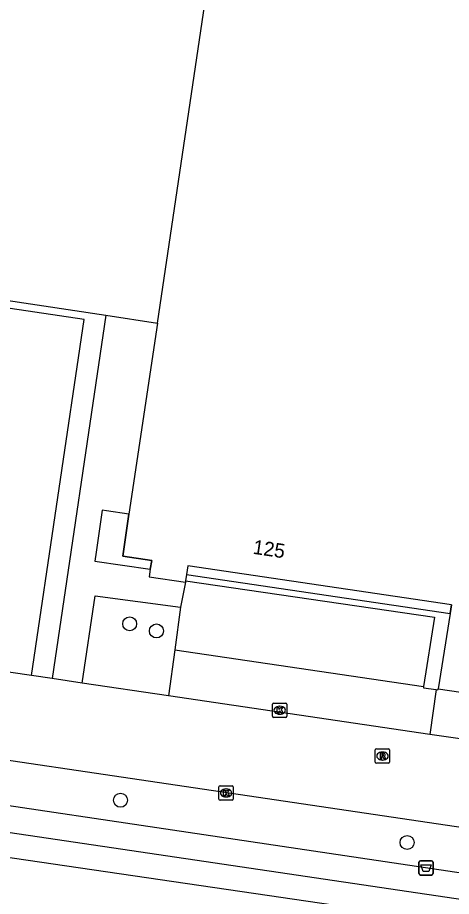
# Model space of a CAD drawing. Extents: x 163686 to 164493, y 382719 to 383870.
# Drawn here: x 163728.6 to 163758.9, y 382784.3 to 382845.8 of the extents above; entities that cross this region are included whole.
import ezdxf

# ---------------------------------------------------------------- set-up
doc = ezdxf.new("R2010")
doc.units = 0
for name, color, linetype in [('IMGEO_Afvalbak', 7, 'Continuous'), ('IMGEO_Boom', 7, 'Continuous'), ('IMGEO_Fietspad_open', 7, 'Continuous'), ('IMGEO_Groenvoorziening', 7, 'Continuous'), ('IMGEO_Kolk', 7, 'Continuous'), ('IMGEO_Pand', 7, 'Continuous'), ('IMGEO_Pand_nummerreeks', 7, 'Continuous'), ('IMGEO_Pand_overbouw', 7, 'Continuous'), ('IMGEO_Parkeervlak_halfverhard', 7, 'Continuous'), ('IMGEO_Parkeervlak_open', 7, 'Continuous'), ('IMGEO_Rijbaan_lokaal_open', 7, 'Continuous'), ('IMGEO_Rioolput', 7, 'Continuous'), ('IMGEO_Voetpad_open', 7, 'Continuous'), ('IMGEO_Waterloop', 7, 'Continuous')]:
    doc.layers.add(name, color=color, linetype=linetype)

msp = doc.modelspace()

# ---------------------------------------------------------------- linework, layer by layer
at = {"layer": 'IMGEO_Afvalbak'}
for p, q in [((163756.643, 382785.871), (163756.643, 382786.671)), ((163756.643, 382786.671), (163756.643, 382785.871)), ((163756.743, 382786.771), (163757.533, 382786.771)), ((163757.533, 382786.771), (163756.743, 382786.771)), ((163757.633, 382786.671), (163757.633, 382785.871)), ((163757.633, 382785.871), (163757.633, 382786.671)), ((163757.533, 382785.771), (163756.743, 382785.771)), ((163756.743, 382785.771), (163757.533, 382785.771))]:
    msp.add_line(p, q, dxfattribs=at)
msp.add_lwpolyline([(163756.786, 382786.485), (163757.49, 382786.485), (163757.341, 382786.015), (163756.935, 382786.015), (163756.786, 382786.485)], dxfattribs=at)
for centre, start, end in [((163756.743, 382786.671), 90, 180), ((163756.743, 382786.671), 90, 180), ((163757.533, 382786.671), 0, 90), ((163757.533, 382786.671), 360, 90), ((163756.743, 382785.871), 180, 270), ((163756.743, 382785.871), 180, 270), ((163757.533, 382785.871), 270, 0), ((163757.533, 382785.871), 270, 0)]:
    msp.add_arc(centre, 0.1, start, end, dxfattribs=at)
at = {"layer": 'IMGEO_Boom'}
for centre in [(163736.411, 382803.347), (163738.281, 382802.85), (163735.772, 382791.006), (163755.814, 382788.046)]:
    msp.add_circle(centre, 0.489, dxfattribs=at)
at = {"layer": 'IMGEO_Fietspad_open'}
for points in [[(163764.154, 382785.228), (163700.855, 382794.642), (163698.697, 382794.967)], [(163938.698, 382757.534), (163796.75, 382778.554), (163700.774, 382792.768), (163698.458, 382793.117)]]:
    msp.add_lwpolyline(points, dxfattribs=at)
at = {"layer": 'IMGEO_Groenvoorziening'}
msp.add_lwpolyline([(163703.742, 382829.606), (163734.753, 382824.935)], dxfattribs=at)
at = {"layer": 'IMGEO_Kolk'}
for p, q in [((163746.406, 382796.879), (163746.406, 382797.731)), ((163746.481, 382797.805), (163747.333, 382797.805)), ((163746.894, 382797.585), (163746.919, 382797.585)), ((163747.407, 382797.731), (163747.407, 382796.879)), ((163746.917, 382797.025), (163746.892, 382797.025)), ((163747.333, 382796.805), (163746.481, 382796.805)), ((163742.656, 382791.087), (163742.656, 382791.939)), ((163742.731, 382792.013), (163743.583, 382792.013)), ((163743.657, 382791.939), (163743.657, 382791.087)), ((163743.144, 382791.793), (163743.169, 382791.793)), ((163743.583, 382791.013), (163742.731, 382791.013)), ((163743.167, 382791.233), (163743.142, 382791.233))]:
    msp.add_line(p, q, dxfattribs=at)
for points in [[(163746.406, 382796.879), (163746.406, 382797.731)], [(163746.481, 382797.805), (163747.333, 382797.805)], [(163746.727, 382797.505), (163746.85, 382797.505), (163746.85, 382797.354), (163746.98, 382797.505), (163747.144, 382797.505), (163746.998, 382797.354), (163747.151, 382797.105), (163746.999, 382797.105), (163746.914, 382797.269), (163746.85, 382797.202), (163746.85, 382797.105), (163746.727, 382797.105), (163746.727, 382797.505)], [(163747.407, 382797.731), (163747.407, 382796.879)], [(163747.333, 382796.805), (163746.481, 382796.805)], [(163742.656, 382791.087), (163742.656, 382791.939)], [(163742.731, 382792.013), (163743.583, 382792.013)], [(163743.657, 382791.939), (163743.657, 382791.087)], [(163742.977, 382791.713), (163743.1, 382791.713), (163743.1, 382791.562), (163743.23, 382791.713), (163743.394, 382791.713), (163743.248, 382791.562), (163743.401, 382791.313), (163743.249, 382791.313), (163743.164, 382791.477), (163743.1, 382791.41), (163743.1, 382791.313), (163742.977, 382791.313), (163742.977, 382791.713)], [(163743.583, 382791.013), (163742.731, 382791.013)]]:
    msp.add_lwpolyline(points, dxfattribs=at)
for centre, start, end in [((163746.483, 382797.729), 91.55205, 178.44795), ((163746.483, 382797.729), 91.55205, 178.44795), ((163747.331, 382797.729), 1.55205, 88.44795), ((163747.331, 382797.729), 1.55205, 88.44795), ((163746.483, 382796.881), 181.55205, 268.44795), ((163746.483, 382796.881), 181.55205, 268.44795), ((163747.331, 382796.881), 271.55205, 358.44795), ((163747.331, 382796.881), 271.55205, 358.44795), ((163742.733, 382791.937), 91.55205, 178.44795), ((163742.733, 382791.937), 91.55205, 178.44795), ((163743.581, 382791.937), 1.55205, 88.44795), ((163743.581, 382791.937), 1.55205, 88.44795), ((163742.733, 382791.089), 181.55205, 268.44795), ((163742.733, 382791.089), 181.55205, 268.44795), ((163743.581, 382791.089), 271.55205, 358.44795), ((163743.581, 382791.089), 271.55205, 358.44795)]:
    msp.add_arc(centre, 0.0765, start, end, dxfattribs=at)
for centre, major_axis, ratio, start_param, end_param in [((163746.893, 382797.305), (-0.387, 0.002), 0.722429, 4.712389, 7.853982), ((163746.918, 382797.305), (-0.39, 0.002), 0.717154, 1.570796, 4.712389), ((163743.143, 382791.513), (-0.387, 0.002), 0.722429, 4.712389, 7.853982), ((163743.168, 382791.513), (-0.39, 0.002), 0.717154, 1.570796, 4.712389)]:
    msp.add_ellipse(centre, major_axis=major_axis, ratio=ratio, start_param=start_param, end_param=end_param, dxfattribs=at)
at = {"layer": 'IMGEO_Pand'}
for points in [[(163738.347, 382824.393), (163744.772, 382867.667), (163767.747, 382864.255), (163761.467, 382821.887)], [(163738.347, 382824.393), (163736.362, 382811.027), (163735.926, 382808.089), (163737.957, 382807.783), (163737.854, 382807.162), (163737.767, 382806.638), (163740.305, 382806.259)], [(163758.915, 382804.671), (163740.469, 382807.408), (163740.381, 382806.79), (163740.32, 382806.366)], [(163740.32, 382806.366), (163740.305, 382806.259)], [(163758.918, 382804.688), (163758.915, 382804.671)]]:
    msp.add_lwpolyline(points, dxfattribs=at)
at = {"layer": 'IMGEO_Pand_overbouw'}
for points in [[(163736.362, 382811.027), (163734.794, 382811.265), (163734.494, 382811.311), (163734.06, 382808.371), (163733.966, 382807.734), (163737.854, 382807.162), (163737.957, 382807.783), (163735.926, 382808.089)], [(163758.915, 382804.671), (163740.469, 382807.408), (163740.381, 382806.79), (163758.827, 382804.076)]]:
    msp.add_lwpolyline(points, close=True, dxfattribs=at)
at = {"layer": 'IMGEO_Parkeervlak_halfverhard'}
msp.add_lwpolyline([(163739.978, 382804.514), (163739.565, 382801.532)], dxfattribs=at)
at = {"layer": 'IMGEO_Parkeervlak_open'}
msp.add_lwpolyline([(163729.55, 382799.728), (163733.236, 382824.631), (163705.132, 382828.814), (163702.804, 382812.996), (163727.391, 382809.337)], dxfattribs=at)
at = {"layer": 'IMGEO_Rijbaan_lokaal_open'}
for points in [[(163734.753, 382824.935), (163730.997, 382799.514)], [(163734.753, 382824.935), (163738.347, 382824.393)], [(163740.305, 382806.259), (163739.978, 382804.514)], [(163733.089, 382799.205), (163733.993, 382805.314), (163739.978, 382804.514)], [(163729.55, 382799.728), (163726.477, 382800.182)], [(163730.997, 382799.514), (163729.55, 382799.728)], [(163733.089, 382799.205), (163730.997, 382799.514)], [(163739.118, 382798.314), (163733.089, 382799.205)], [(163757.401, 382795.612), (163739.118, 382798.314)], [(163701.006, 382797.795), (163761.168, 382788.88)], [(163760.998, 382795.081), (163757.401, 382795.612)]]:
    msp.add_lwpolyline(points, dxfattribs=at)
at = {"layer": 'IMGEO_Rioolput'}
for p, q in [((163753.593, 382793.674), (163753.593, 382794.526)), ((163753.668, 382794.6), (163754.52, 382794.6)), ((163754.594, 382794.526), (163754.594, 382793.674)), ((163754.104, 382793.82), (163754.079, 382793.82)), ((163754.081, 382794.38), (163754.106, 382794.38)), ((163754.52, 382793.6), (163753.668, 382793.6))]:
    msp.add_line(p, q, dxfattribs=at)
for points in [[(163753.593, 382793.674), (163753.593, 382794.526)], [(163753.668, 382794.6), (163754.52, 382794.6)], [(163754.594, 382794.526), (163754.594, 382793.674)], [(163754.182, 382794.298), (163753.93, 382794.3), (163753.93, 382793.9)], [(163753.93, 382793.9), (163754.054, 382793.9), (163754.054, 382794.062), (163754.065, 382794.062)], [(163754.108, 382794.219), (163754.054, 382794.219), (163754.054, 382794.138)], [(163754.054, 382794.138), (163754.106, 382794.138)], [(163754.112, 382794.033), (163754.183, 382793.9), (163754.323, 382793.9), (163754.258, 382794.026)], [(163754.52, 382793.6), (163753.668, 382793.6)]]:
    msp.add_lwpolyline(points, dxfattribs=at)
for centre, radius, start, end in [((163753.67, 382794.524), 0.0765, 91.55205, 178.44795), ((163753.67, 382794.524), 0.0765, 91.55205, 178.44795), ((163754.518, 382794.524), 0.0765, 1.55205, 88.44795), ((163754.518, 382794.524), 0.0765, 1.55205, 88.44795), ((163754.064, 382794.009), 0.0533, 26.02933, 88.69889), ((163754.09, 382794.327), 0.19, 274.7715, 282.96867), ((163754.114, 382794.123), 0.0964, 77.00612, 93.18647), ((163754.128, 382794.18), 0.0378, 276.66336, 79.67722), ((163754.181, 382794.188), 0.109, 350.36119, 89.41601), ((163754.179, 382794.188), 0.112, 277.58423, 350.98172), ((163754.163, 382793.973), 0.108, 29.51342, 73.79051), ((163753.67, 382793.676), 0.0765, 181.55205, 268.44795), ((163753.67, 382793.676), 0.0765, 181.55205, 268.44795), ((163754.518, 382793.676), 0.0765, 271.55205, 358.44795), ((163754.518, 382793.676), 0.0765, 271.55205, 358.44795)]:
    msp.add_arc(centre, radius, start, end, dxfattribs=at)
for centre, major_axis, ratio, start_param, end_param in [((163754.08, 382794.1), (-0.387, 0.002), 0.722429, 4.712389, 7.853982), ((163754.105, 382794.1), (-0.39, 0.002), 0.717154, 1.570796, 4.712389)]:
    msp.add_ellipse(centre, major_axis=major_axis, ratio=ratio, start_param=start_param, end_param=end_param, dxfattribs=at)
at = {"layer": 'IMGEO_Voetpad_open'}
for points in [[(163740.32, 382806.366), (163757.74, 382803.803), (163756.972, 382798.955)], [(163758.915, 382804.671), (163758.827, 382804.076), (163757.985, 382798.809)], [(163739.565, 382801.532), (163739.118, 382798.314)], [(163739.565, 382801.532), (163756.972, 382798.955)], [(163756.972, 382798.955), (163756.96, 382798.881), (163757.852, 382798.752)], [(163757.852, 382798.752), (163757.401, 382795.612)], [(163757.852, 382798.752), (163757.973, 382798.734), (163757.985, 382798.809)], [(163757.985, 382798.809), (163761.33, 382798.315)]]:
    msp.add_lwpolyline(points, dxfattribs=at)
at = {"layer": 'IMGEO_Waterloop'}
msp.add_lwpolyline([(163937.736, 382750.939), (163937.689, 382750.615), (163909.128, 382760.464), (163795.709, 382777.072), (163698.229, 382791.347), (163685.611, 382793.195)], dxfattribs=at)

# ---------------------------------------------------------------- texts
at = {"layer": 'IMGEO_Pand_nummerreeks'}
msp.add_text('125', height=1, rotation=351.56033, dxfattribs=at).set_placement((163744.989, 382808.254))

doc.saveas('drawing.dxf')
